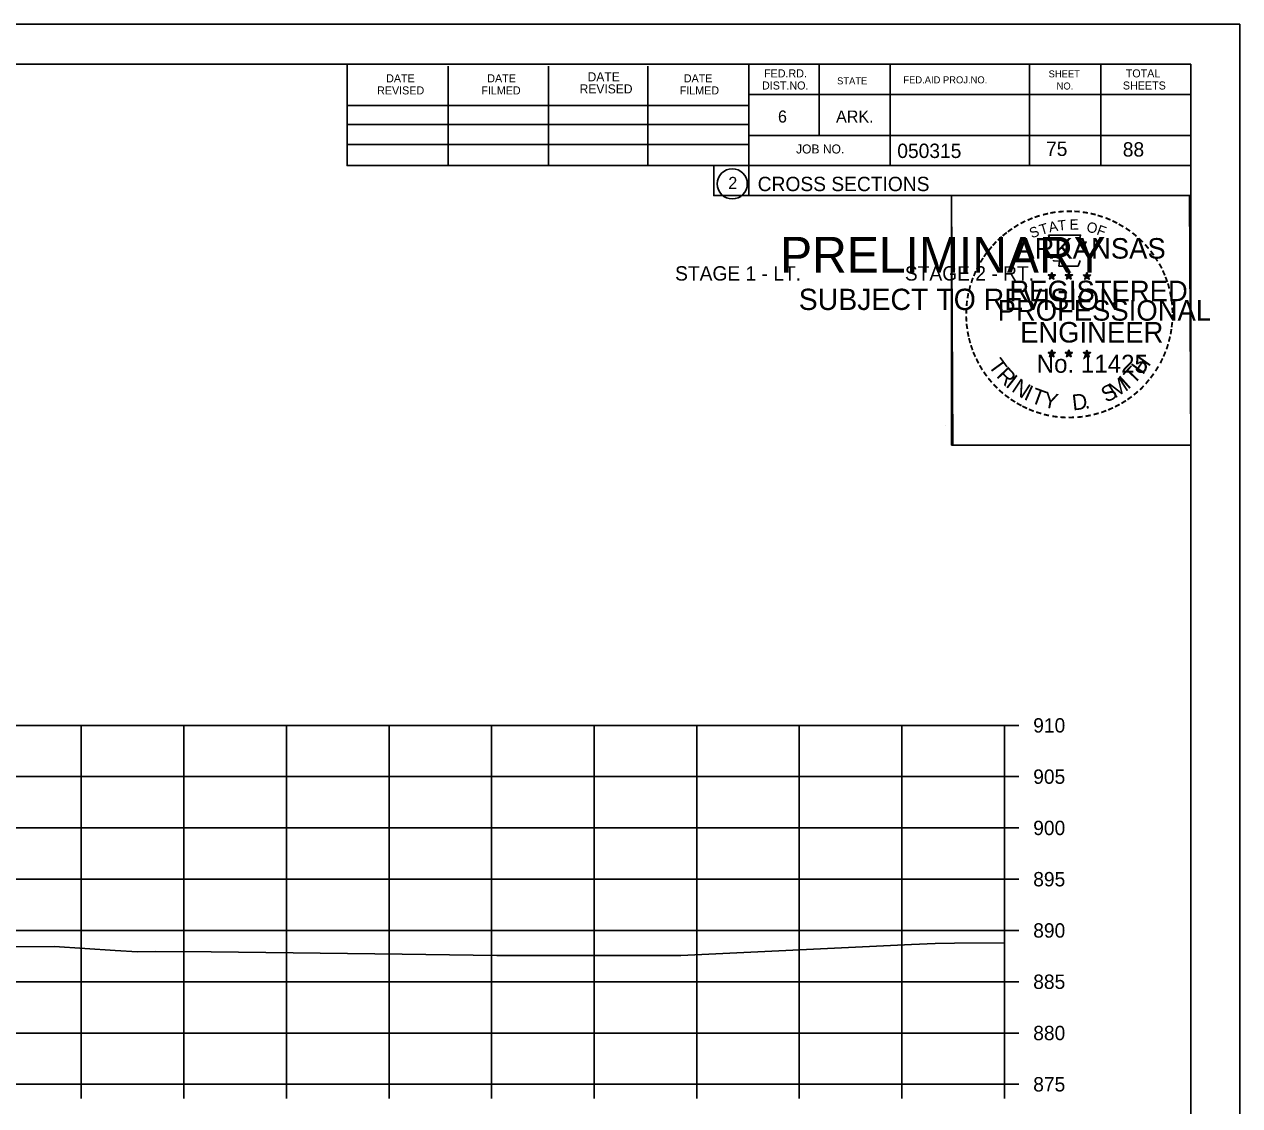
# Model space of a CAD drawing. Extents: x 1486524 to 1499135, y 326561 to 337924.
# Drawn here: x 1489027.3 to 1489145.8, y 333527.2 to 333632.7 of the extents above; entities that cross this region are included whole.
import ezdxf

# ---------------------------------------------------------------- set-up
doc = ezdxf.new("R2010")
doc.units = 0
for name, color, linetype in [('Default', 7, 'Continuous'), ('E_Const Align', 7, 'Continuous'), ('E_Const Align Station', 7, 'Continuous'), ('E_Ownership Information', 7, 'Continuous'), ('E_Property Line', 7, 'Continuous'), ('E_Quarter Calls', 7, 'Continuous'), ('E_Section Line', 7, 'Continuous'), ('E_Station Offset', 7, 'Continuous'), ('E_Tract Number', 7, 'Continuous'), ('S_SIXTEEN_SECTION', 7, 'Continuous')]:
    doc.layers.add(name, color=color, linetype=linetype)

msp = doc.modelspace()

# ---------------------------------------------------------------- linework, layer by layer
at = {"layer": 'E_Const Align'}
for p, q in [((1489122.89, 333529.3), (1489122.89, 333564.3)), ((1489124.29, 333564.3), (1489122.89, 333564.3)), ((1489124.29, 333559.3), (1489122.89, 333559.3)), ((1489124.29, 333554.3), (1489122.89, 333554.3)), ((1489124.29, 333549.3), (1489122.89, 333549.3)), ((1489124.29, 333544.3), (1489122.89, 333544.3)), ((1489124.29, 333539.3), (1489122.89, 333539.3)), ((1489124.29, 333534.3), (1489122.89, 333534.3)), ((1488842.89, 333529.3), (1489122.89, 333529.3)), ((1489032.89, 333527.9), (1489032.89, 333529.3)), ((1489042.89, 333527.9), (1489042.89, 333529.3)), ((1489052.89, 333527.9), (1489052.89, 333529.3)), ((1489062.89, 333527.9), (1489062.89, 333529.3)), ((1489072.89, 333527.9), (1489072.89, 333529.3)), ((1489082.89, 333527.9), (1489082.89, 333529.3)), ((1489092.89, 333527.9), (1489092.89, 333529.3)), ((1489102.89, 333527.9), (1489102.89, 333529.3)), ((1489112.89, 333527.9), (1489112.89, 333529.3)), ((1489122.89, 333527.9), (1489122.89, 333529.3)), ((1489124.29, 333529.3), (1489122.89, 333529.3))]:
    msp.add_line(p, q, dxfattribs=at)
at = {"layer": 'E_Ownership Information'}
for p, q in [((1488842.89, 333564.3), (1489122.89, 333564.3)), ((1488842.89, 333564.3), (1489122.89, 333564.3)), ((1489032.89, 333529.3), (1489032.89, 333564.3)), ((1489032.89, 333529.3), (1489032.89, 333564.3)), ((1489042.89, 333529.3), (1489042.89, 333564.3)), ((1489042.89, 333529.3), (1489042.89, 333564.3)), ((1489052.89, 333529.3), (1489052.89, 333564.3)), ((1489052.89, 333529.3), (1489052.89, 333564.3)), ((1489062.89, 333529.3), (1489062.89, 333564.3)), ((1489062.89, 333529.3), (1489062.89, 333564.3)), ((1489072.89, 333529.3), (1489072.89, 333564.3)), ((1489072.89, 333529.3), (1489072.89, 333564.3)), ((1489082.89, 333529.3), (1489082.89, 333564.3)), ((1489082.89, 333529.3), (1489082.89, 333564.3)), ((1489092.89, 333529.3), (1489092.89, 333564.3)), ((1489092.89, 333529.3), (1489092.89, 333564.3)), ((1489102.89, 333529.3), (1489102.89, 333564.3)), ((1489102.89, 333529.3), (1489102.89, 333564.3)), ((1489112.89, 333529.3), (1489112.89, 333564.3)), ((1489112.89, 333529.3), (1489112.89, 333564.3)), ((1489122.89, 333529.3), (1489122.89, 333564.3)), ((1489122.89, 333529.3), (1489122.89, 333564.3)), ((1488842.89, 333559.3), (1489122.89, 333559.3)), ((1488842.89, 333559.3), (1489122.89, 333559.3)), ((1488842.89, 333554.3), (1489122.89, 333554.3)), ((1488842.89, 333554.3), (1489122.89, 333554.3)), ((1488842.89, 333549.3), (1489122.89, 333549.3)), ((1488842.89, 333549.3), (1489122.89, 333549.3)), ((1488842.89, 333544.3), (1489122.89, 333544.3)), ((1488842.89, 333544.3), (1489122.89, 333544.3)), ((1488842.89, 333539.3), (1489122.89, 333539.3)), ((1488842.89, 333539.3), (1489122.89, 333539.3)), ((1488842.89, 333534.3), (1489122.89, 333534.3)), ((1488842.89, 333534.3), (1489122.89, 333534.3)), ((1488842.89, 333529.3), (1489122.89, 333529.3)), ((1488842.89, 333529.3), (1489122.89, 333529.3))]:
    msp.add_line(p, q, dxfattribs=at)
at = {"layer": 'E_Property Line'}
for p, q in [((1488824.89, 333628.76), (1489141.07, 333628.76)), ((1489058.81, 333618.88), (1489058.81, 333628.76)), ((1489068.67, 333618.88), (1489068.67, 333628.56)), ((1489078.43, 333618.88), (1489078.43, 333628.56)), ((1489088.11, 333618.88), (1489088.11, 333628.56)), ((1489097.97, 333628.76), (1489097.97, 333615.96)), ((1489104.81, 333628.76), (1489104.81, 333621.82)), ((1489111.75, 333628.76), (1489111.75, 333618.88)), ((1489125.33, 333628.76), (1489125.33, 333618.88)), ((1489132.27, 333628.76), (1489132.27, 333618.88)), ((1489141.07, 333423.3), (1489141.07, 333628.76)), ((1489141.07, 333625.82), (1489097.97, 333625.82)), ((1489141.07, 333625.84), (1489141.07, 333625.84)), ((1489058.81, 333624.74), (1489097.97, 333624.74)), ((1489058.81, 333622.88), (1489097.97, 333622.88)), ((1489141.07, 333621.82), (1489097.97, 333621.82)), ((1489100.93, 333621.82), (1489141.07, 333621.82)), ((1489058.81, 333618.88), (1489058.81, 333620.94)), ((1489058.81, 333620.94), (1489097.97, 333620.94)), ((1489141.07, 333618.88), (1489058.81, 333618.88)), ((1489097.97, 333615.96), (1489141.07, 333615.96))]:
    msp.add_line(p, q, dxfattribs=at)
msp.add_circle((1489096.35, 333617.1), 1.47, dxfattribs=at)
at = {"layer": 'E_Quarter Calls'}
for p, q in [((1488812.48, 333632.66), (1489145.82, 333632.66)), ((1489117.1, 333593.51), (1489117.1, 333593.51))]:
    msp.add_line(p, q, dxfattribs=at)
for points in [[(1488812.48, 333632.66), (1489145.82, 333632.66), (1489145.82, 333419.32), (1488812.48, 333419.32)], [(1489058.81, 333628.76), (1489058.81, 333618.88), (1489094.54, 333618.88), (1489094.54, 333615.96), (1489117.74, 333615.96), (1489117.74, 333591.63), (1489141.07, 333591.63), (1489141.07, 333423.3), (1488824.89, 333423.3), (1488824.89, 333628.76)], [(1489117.74, 333615.96), (1489140.94, 333615.96), (1489141.07, 333591.63), (1489117.86, 333591.63)]]:
    msp.add_lwpolyline(points, close=True, dxfattribs=at)
at = {"layer": 'E_Tract Number'}
msp.add_lwpolyline([(1489024.63, 333542.69), (1489030.28, 333542.73), (1489036.2, 333542.36), (1489038.36, 333542.23), (1489040.15, 333542.24), (1489045.56, 333542.22), (1489064.18, 333542), (1489073.39, 333541.87), (1489076.02, 333541.86), (1489091.33, 333541.87), (1489113.83, 333542.92), (1489116.12, 333543.03), (1489118.03, 333543.06), (1489122.89, 333543.11)], dxfattribs=at)
at = {"layer": 'S_SIXTEEN_SECTION'}
for p, q in [((1489127.15, 333608.22), (1489127.5, 333608.11)), ((1489127.15, 333608.22), (1489127.4, 333608.17)), ((1489127.15, 333608.22), (1489127.39, 333608.1)), ((1489127.28, 333607.81), (1489127.5, 333608.11)), ((1489127.28, 333607.81), (1489127.41, 333608.05)), ((1489127.28, 333607.81), (1489127.5, 333608.03)), ((1489127.5, 333608.47), (1489127.46, 333608.22)), ((1489127.5, 333608.11), (1489127.5, 333608.47)), ((1489127.5, 333608.47), (1489127.55, 333608.22)), ((1489127.85, 333608.22), (1489127.5, 333608.11)), ((1489127.71, 333607.81), (1489127.5, 333608.11)), ((1489127.71, 333607.81), (1489127.5, 333608.02)), ((1489127.85, 333608.22), (1489127.56, 333608.17)), ((1489127.71, 333607.81), (1489127.58, 333608.1)), ((1489127.85, 333608.22), (1489127.64, 333608.12)), ((1489128.82, 333608.22), (1489129.17, 333608.11)), ((1489128.82, 333608.22), (1489129.07, 333608.17)), ((1489128.82, 333608.22), (1489129.06, 333608.1)), ((1489128.95, 333607.81), (1489129.17, 333608.11)), ((1489128.95, 333607.81), (1489129.08, 333608.05)), ((1489128.95, 333607.81), (1489129.17, 333608.03)), ((1489129.17, 333608.47), (1489129.13, 333608.22)), ((1489129.17, 333608.11), (1489129.17, 333608.47)), ((1489129.17, 333608.47), (1489129.22, 333608.22)), ((1489129.52, 333608.22), (1489129.17, 333608.11)), ((1489129.38, 333607.81), (1489129.17, 333608.11)), ((1489129.38, 333607.81), (1489129.17, 333608.02)), ((1489129.52, 333608.22), (1489129.23, 333608.17)), ((1489129.38, 333607.81), (1489129.25, 333608.1)), ((1489129.52, 333608.22), (1489129.31, 333608.12)), ((1489130.58, 333608.21), (1489130.93, 333608.1)), ((1489130.58, 333608.21), (1489130.84, 333608.16)), ((1489130.58, 333608.21), (1489130.82, 333608.08)), ((1489130.72, 333607.8), (1489130.93, 333608.1)), ((1489130.72, 333607.8), (1489130.84, 333608.04)), ((1489130.72, 333607.8), (1489130.93, 333608.02)), ((1489130.93, 333608.46), (1489130.89, 333608.21)), ((1489130.93, 333608.1), (1489130.93, 333608.46)), ((1489130.93, 333608.46), (1489130.98, 333608.21)), ((1489131.28, 333608.21), (1489130.93, 333608.1)), ((1489131.15, 333607.8), (1489130.93, 333608.1)), ((1489131.15, 333607.8), (1489130.93, 333608.01)), ((1489131.28, 333608.21), (1489130.99, 333608.16)), ((1489131.15, 333607.8), (1489131.01, 333608.09)), ((1489131.28, 333608.21), (1489131.08, 333608.1)), ((1489127.15, 333600.65), (1489127.5, 333600.53)), ((1489127.15, 333600.65), (1489127.4, 333600.6)), ((1489127.15, 333600.65), (1489127.38, 333600.52)), ((1489127.28, 333600.24), (1489127.5, 333600.53)), ((1489127.28, 333600.24), (1489127.41, 333600.48)), ((1489127.28, 333600.24), (1489127.49, 333600.45)), ((1489127.5, 333600.9), (1489127.45, 333600.65)), ((1489127.71, 333600.24), (1489127.49, 333600.45)), ((1489127.5, 333600.53), (1489127.5, 333600.9)), ((1489127.5, 333600.9), (1489127.54, 333600.65)), ((1489127.84, 333600.65), (1489127.5, 333600.53)), ((1489127.71, 333600.24), (1489127.5, 333600.53)), ((1489127.84, 333600.65), (1489127.56, 333600.6)), ((1489127.71, 333600.24), (1489127.57, 333600.53)), ((1489127.84, 333600.65), (1489127.64, 333600.54)), ((1489128.82, 333600.65), (1489129.16, 333600.53)), ((1489128.82, 333600.65), (1489129.07, 333600.6)), ((1489128.82, 333600.65), (1489129.05, 333600.52)), ((1489128.95, 333600.24), (1489129.16, 333600.53)), ((1489128.95, 333600.24), (1489129.07, 333600.48)), ((1489128.95, 333600.24), (1489129.16, 333600.45)), ((1489129.16, 333600.9), (1489129.12, 333600.65)), ((1489129.16, 333600.53), (1489129.16, 333600.9)), ((1489129.16, 333600.9), (1489129.21, 333600.65)), ((1489129.51, 333600.65), (1489129.16, 333600.53)), ((1489129.38, 333600.24), (1489129.16, 333600.53)), ((1489129.38, 333600.24), (1489129.16, 333600.45)), ((1489129.51, 333600.65), (1489129.23, 333600.6)), ((1489129.38, 333600.24), (1489129.24, 333600.53)), ((1489129.51, 333600.65), (1489129.31, 333600.54)), ((1489130.58, 333600.64), (1489130.93, 333600.52)), ((1489130.58, 333600.64), (1489130.84, 333600.59)), ((1489130.58, 333600.64), (1489130.82, 333600.51)), ((1489130.72, 333600.23), (1489130.93, 333600.52)), ((1489130.72, 333600.23), (1489130.84, 333600.47)), ((1489130.72, 333600.23), (1489130.93, 333600.44)), ((1489130.93, 333600.89), (1489130.89, 333600.64)), ((1489130.93, 333600.52), (1489130.93, 333600.89)), ((1489130.93, 333600.89), (1489130.98, 333600.64)), ((1489131.28, 333600.64), (1489130.93, 333600.52)), ((1489131.14, 333600.23), (1489130.93, 333600.52)), ((1489131.14, 333600.23), (1489130.93, 333600.44)), ((1489131.28, 333600.64), (1489130.99, 333600.59)), ((1489131.14, 333600.23), (1489131.01, 333600.52)), ((1489131.28, 333600.64), (1489131.07, 333600.53))]:
    msp.add_line(p, q, dxfattribs=at)
for points in [[(1489127.19, 333612.1), (1489127.46, 333611.27)], [(1489130.7, 333611.17), (1489130.84, 333611.46), (1489130.16, 333611.43), (1489130.31, 333612.1), (1489127.19, 333612.1)], [(1489127.68, 333609.67), (1489127.68, 333609.59), (1489128.25, 333609.57), (1489128.19, 333609.09), (1489130.06, 333609.09), (1489130.26, 333609.63)], [(1489127.5, 333608.47), (1489127.71, 333607.81), (1489127.15, 333608.22), (1489127.85, 333608.22), (1489127.28, 333607.81), (1489127.5, 333608.47)], [(1489129.17, 333608.47), (1489129.38, 333607.81), (1489128.82, 333608.22), (1489129.52, 333608.22), (1489128.95, 333607.81), (1489129.17, 333608.47)], [(1489130.93, 333608.46), (1489131.15, 333607.8), (1489130.58, 333608.21), (1489131.28, 333608.21), (1489130.72, 333607.8), (1489130.93, 333608.46)], [(1489127.5, 333600.9), (1489127.71, 333600.24), (1489127.15, 333600.65), (1489127.84, 333600.65), (1489127.28, 333600.24), (1489127.5, 333600.9)], [(1489129.16, 333600.9), (1489129.38, 333600.24), (1489128.82, 333600.65), (1489129.51, 333600.65), (1489128.95, 333600.24), (1489129.16, 333600.9)], [(1489130.93, 333600.89), (1489131.14, 333600.23), (1489130.58, 333600.64), (1489131.28, 333600.64), (1489130.72, 333600.23), (1489130.93, 333600.89)]]:
    msp.add_lwpolyline(points, dxfattribs=at)
for centre, radius in [((1489127.5, 333608.11), 0.172), ((1489127.5, 333608.11), 0.145), ((1489127.5, 333608.11), 0.116), ((1489127.5, 333608.11), 0.0991), ((1489127.5, 333608.11), 0.0747), ((1489127.5, 333608.11), 0.0495), ((1489127.5, 333608.11), 0.0296), ((1489129.17, 333608.11), 0.172), ((1489129.17, 333608.11), 0.145), ((1489129.17, 333608.11), 0.116), ((1489129.17, 333608.11), 0.0991), ((1489129.17, 333608.11), 0.0747), ((1489129.17, 333608.11), 0.0495), ((1489129.17, 333608.11), 0.0296), ((1489130.93, 333608.09), 0.172), ((1489130.93, 333608.09), 0.145), ((1489130.93, 333608.09), 0.116), ((1489130.93, 333608.09), 0.0991), ((1489130.93, 333608.09), 0.0747), ((1489130.93, 333608.09), 0.0495), ((1489130.93, 333608.09), 0.0296), ((1489127.49, 333600.53), 0.172), ((1489127.49, 333600.53), 0.145), ((1489127.49, 333600.53), 0.116), ((1489127.49, 333600.53), 0.0991), ((1489127.49, 333600.53), 0.0747), ((1489127.49, 333600.53), 0.0495), ((1489127.49, 333600.53), 0.0296), ((1489129.16, 333600.53), 0.172), ((1489129.16, 333600.53), 0.145), ((1489129.16, 333600.53), 0.116), ((1489129.16, 333600.53), 0.0991), ((1489129.16, 333600.53), 0.0747), ((1489129.16, 333600.53), 0.0495), ((1489129.16, 333600.53), 0.0296), ((1489130.93, 333600.52), 0.172), ((1489130.93, 333600.52), 0.145), ((1489130.93, 333600.52), 0.116), ((1489130.93, 333600.52), 0.0991), ((1489130.93, 333600.52), 0.0747), ((1489130.93, 333600.52), 0.0495), ((1489130.93, 333600.52), 0.0296)]:
    msp.add_circle(centre, radius, dxfattribs=at)

# ---------------------------------------------------------------- texts
at = {"layer": 'Default'}
for s, p in [('STAGE 1 - LT.', (1489090.78, 333607.67)), ('STAGE 2 - RT.', (1489113.18, 333607.67))]:
    msp.add_text(s, height=1.4, dxfattribs=at).set_placement(p)
at = {"layer": 'E_Const Align Station'}
for s, p in [('910', (1489125.69, 333563.6)), ('905', (1489125.69, 333558.6)), ('900', (1489125.69, 333553.6)), ('895', (1489125.69, 333548.6)), ('890', (1489125.69, 333543.6)), ('885', (1489125.69, 333538.6)), ('880', (1489125.69, 333533.6)), ('875', (1489125.69, 333528.6))]:
    msp.add_text(s, height=1.4, dxfattribs=at).set_placement(p)
at = {"layer": 'E_Property Line'}
for s, height, p in [('DATE', 0.782, (1489062.61, 333627)), ('DATE', 0.782, (1489072.47, 333627)), ('DATE', 0.879, (1489082.25, 333627.1)), ('DATE', 0.782, (1489091.63, 333627)), ('FED.RD.', 0.782, (1489099.45, 333627.48)), ('SHEET', 0.684, (1489127.19, 333627.48)), ('TOTAL', 0.782, (1489134.71, 333627.48)), ('REVISED', 0.782, (1489061.73, 333625.82)), ('FILMED', 0.782, (1489071.89, 333625.82)), ('REVISED', 0.879, (1489081.47, 333625.92)), ('FILMED', 0.782, (1489091.23, 333625.82)), ('DIST.NO.', 0.782, (1489099.25, 333626.3)), ('STATE', 0.684, (1489106.57, 333626.8)), ('FED.AID PROJ.NO.', 0.684, (1489113.03, 333626.9)), ('NO.', 0.684, (1489127.97, 333626.3)), ('SHEETS', 0.782, (1489134.43, 333626.3)), ('6', 1.17, (1489100.81, 333623.08)), ('ARK.', 1.172, (1489106.47, 333623.08)), ('JOB NO.', 0.879, (1489102.57, 333620.06)), ('050315', 1.4, (1489112.44, 333619.62)), ('2', 1.17, (1489095.97, 333616.61)), ('CROSS SECTIONS', 1.4, (1489098.83, 333616.39))]:
    msp.add_text(s, height=height, rotation=360, dxfattribs=at).set_placement(p)
at = {"layer": 'E_Section Line'}
for s, height, p in [('PRELIMINARY', 3.5, (1489101.02, 333608.43)), ('DWB', 0.01, (1489101.76, 333610.28)), ('SUBJECT TO REVISION', 2.0751, (1489102.83, 333604.8))]:
    msp.add_text(s, height=height, rotation=360, dxfattribs=at).set_placement(p)
at = {"layer": 'E_Station Offset'}
for s, p in [('75', (1489126.94, 333619.82)), ('88', (1489134.42, 333619.76))]:
    msp.add_text(s, height=1.4, dxfattribs=at).set_placement(p)
at = {"layer": 'S_SIXTEEN_SECTION'}
for s, height, rotation, p in [('-', 1.6, 28.7918, (1489124.67, 333612.64)), ('-', 1.6, 24.3072, (1489125.31, 333612.95)), ('-', 1.6, 19.1761, (1489125.94, 333613.22)), ('-', 1.6, 13.6301, (1489126.69, 333613.46)), ('-', 1.6, 10.2193, (1489127.37, 333613.63)), ('T', 1, 6.0228, (1489128.14, 333612.52)), ('-', 1.6, 5.8968, (1489128.1, 333613.74)), ('-', 1.6, 0.1862, (1489128.87, 333613.81)), ('E', 1, 0.8323, (1489129.24, 333612.63)), ('-', 1.6, 357.743, (1489129.59, 333613.8)), ('-', 1.6, 352.1617, (1489130.34, 333613.74)), ('-', 1.6, 347.2049, (1489131.05, 333613.63)), ('-', 1.6, 342.3362, (1489131.69, 333613.47)), ('-', 1.6, 337.8551, (1489132.42, 333613.25)), ('-', 1.6, 334.1211, (1489133.06, 333612.98)), ('-', 1.6, 38.9507, (1489123.02, 333611.49)), ('-', 1.6, 36.2317, (1489123.5, 333611.87)), ('-', 1.6, 34.0636, (1489124.08, 333612.27)), ('S', 1, 21.594, (1489125.55, 333611.77)), ('T', 1, 16.4036, (1489126.46, 333612.11)), ('A', 1, 11.2132, (1489127.29, 333612.36)), ('O', 1, 350.4515, (1489130.84, 333612.42)), ('F', 1, 340.0707, (1489131.8, 333612.19)), ('-', 1.6, 329.6409, (1489133.63, 333612.69)), ('-', 1.6, 325.8627, (1489134.28, 333612.33)), ('-', 1.6, 320.5297, (1489134.89, 333611.91)), ('-', 1.6, 48.423, (1489122.14, 333610.6)), ('-', 1.6, 42.9622, (1489122.59, 333611.08)), ('ARKANSAS', 2, 360, (1489124.04, 333609.81)), ('-', 1.6, 315.5786, (1489135.49, 333611.42)), ('-', 1.6, 309.8797, (1489136.06, 333610.87)), ('-', 1.6, 58.0706, (1489121, 333609.02)), ('-', 1.6, 54.2325, (1489121.32, 333609.55)), ('-', 1.6, 50.6142, (1489121.74, 333610.11)), ('-', 1.6, 306.6522, (1489136.58, 333610.27)), ('-', 1.4, 303.6753, (1489137.07, 333609.7)), ('-', 1.6, 62.8713, (1489120.69, 333608.41)), ('-', 1.6, 299.6684, (1489137.39, 333609.09)), ('-', 1.6, 72.3945, (1489120.21, 333607.16)), ('-', 1.6, 67.7743, (1489120.43, 333607.79)), ('REGISTERED', 2, 360, (1489123.37, 333605.66)), ('DWB', 0.01, 360, (1489127.49, 333608.1)), ('DWB', 0.01, 360, (1489129.16, 333608.1)), ('DWB', 0.01, 360, (1489130.92, 333608.09)), ('-', 1.6, 294.6628, (1489137.71, 333608.48)), ('-', 1.6, 290.5728, (1489137.97, 333607.9)), ('-', 1.6, 81.2013, (1489119.88, 333605.74)), ('-', 1.6, 75.461, (1489120.01, 333606.45)), ('-', 1.6, 285.1233, (1489138.2, 333607.32)), ('-', 1.6, 280.5493, (1489138.4, 333606.58)), ('-', 1.6, 85.1863, (1489119.8, 333605.05)), ('PROFESSIONAL', 2, 360, (1489122.22, 333603.76)), ('-', 1.6, 276.5962, (1489138.56, 333605.81)), ('-', 1.6, 94.1959, (1489119.81, 333603.62)), ('-', 1.6, 89.0622, (1489119.78, 333604.35)), ('-', 1.6, 274.3301, (1489138.62, 333605.09)), ('-', 1.6, 269.9407, (1489138.66, 333604.46)), ('-', 1.6, 98.9479, (1489119.89, 333602.95)), ('ENGINEER', 2, 360, (1489124.41, 333601.63)), ('-', 1.6, 260.9953, (1489138.57, 333603.14)), ('-', 1.6, 263.5172, (1489138.64, 333603.79)), ('-', 1.6, 101.7149, (1489120.02, 333602.22)), ('-', 1.6, 105.4578, (1489120.18, 333601.63)), ('-', 1.6, 255.7626, (1489138.46, 333602.46)), ('-', 1.6, 109.0874, (1489120.4, 333600.99)), ('-', 1.6, 114.0643, (1489120.65, 333600.4)), ('No. 11425', 1.757, 360, (1489126.03, 333598.68)), ('DWB', 0.01, 360, (1489127.48, 333600.53)), ('DWB', 0.01, 360, (1489129.15, 333600.53)), ('DWB', 0.01, 360, (1489130.92, 333600.52)), ('-', 1.6, 247.8887, (1489138.05, 333601.07)), ('-', 1.6, 252.8681, (1489138.28, 333601.74)), ('-', 1.6, 115.7289, (1489120.96, 333599.78)), ('-', 1.6, 120.4471, (1489121.31, 333599.19)), ('T', 1.54, 306.0406, (1489121.25, 333599.37)), ('R', 1.54, 314.005, (1489122.02, 333598.32)), ('T', 1.54, 46.6444, (1489135.49, 333597.47)), ('H', 1.54, 54.6088, (1489136.38, 333598.41)), ('-', 1.6, 239.0712, (1489137.4, 333599.69)), ('-', 1.6, 244.6197, (1489137.79, 333600.44)), ('-', 1.6, 125.8934, (1489121.72, 333598.63)), ('-', 1.6, 130.7181, (1489122.18, 333598.08)), ('I', 1.54, 321.9694, (1489122.92, 333597.39)), ('N', 1.54, 326.5002, (1489123.49, 333596.92)), ('M', 1.54, 32.6563, (1489133.64, 333596.14)), ('I', 1.54, 42.1136, (1489134.92, 333596.99)), ('-', 1.6, 231.2538, (1489136.56, 333598.47)), ('-', 1.6, 233.8452, (1489136.99, 333599.03)), ('-', 1.6, 134.2238, (1489122.7, 333597.54)), ('-', 1.6, 138.9338, (1489123.22, 333597.07)), ('I', 1.54, 335.3603, (1489124.69, 333596.13)), ('T', 1.54, 339.8912, (1489125.35, 333595.81)), ('S', 1.54, 26.9312, (1489132.8, 333595.73)), ('-', 1.6, 221.0851, (1489135.56, 333597.39)), ('-', 1.6, 225.7653, (1489136.09, 333597.9)), ('-', 1.6, 144.6463, (1489123.78, 333596.67)), ('-', 1.6, 148.0898, (1489124.34, 333596.3)), ('-', 1.6, 151.5704, (1489124.92, 333595.97)), ('Y', 1.54, 347.8556, (1489126.57, 333595.36)), ('D', 1.54, 6.3969, (1489129.56, 333595)), ('-', 1.6, 212.2491, (1489134.48, 333596.54)), ('-', 1.6, 215.7363, (1489135.01, 333596.92)), ('-', 1.6, 154.6002, (1489125.44, 333595.72)), ('-', 1.6, 158.5612, (1489126.06, 333595.47)), ('-', 1.6, 162.7983, (1489126.75, 333595.26)), ('-', 1.6, 167.5555, (1489127.46, 333595.09)), ('-', 1.6, 173.1155, (1489128.24, 333594.98)), ('-', 1.6, 191.2858, (1489131.27, 333595.16)), ('.', 1.54, 13.7642, (1489130.75, 333595.13)), ('-', 1.6, 195.4743, (1489132, 333595.36)), ('-', 1.6, 200.7184, (1489132.68, 333595.6)), ('-', 1.6, 204.2516, (1489133.3, 333595.87)), ('-', 1.6, 207.3568, (1489133.92, 333596.19)), ('-', 1.6, 176.5183, (1489128.98, 333594.93)), ('-', 1.6, 181.5918, (1489129.73, 333594.95)), ('-', 1.6, 185.8167, (1489130.54, 333595.02))]:
    msp.add_text(s, height=height, rotation=rotation, dxfattribs=at).set_placement(p)

doc.saveas('drawing.dxf')
